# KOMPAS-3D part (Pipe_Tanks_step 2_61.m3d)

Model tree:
1. X Axis
2. Y Axis
3. Z Axis  (labels: Pipe Dn 50)
     Òîëùèíà ñòåíêè 1 = 1

Referenced files in C:\Documents and Settings\kashirsky\Мои документы\Camtasia Studio\Pipelines3D\Tanks\: Tanks_step 2.a3d
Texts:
  Pipe Dn 50
  Steel ASTM A295
  Three Point Plane
  Plane at Angle
  Line and Point Plane
  Axis through Two Vertices
  Axis of Feature
  Axis of Conical Surface
  Axis through Edge
  Trim by Surface
  Trim by Sketch
  Feature with No History
  Intersection Axis of Two Planes
  Two Line Plane
  Line and Face Plane
  Bend by line
  Hole in sheet body
  Cut in sheet body
  Point in CM
  Linear Dimension from Line to Point
  Surface Finish Symbol
  Geometric Tolerance Symbol
  Leader #1
  Leader #2
  Leader #3
  Shape Deviations and Datum
  Node point number
  Mark of coordination axis
  Node point designation
  Mark/Reference designation with leader
  Mark/reference designation on line
  Mark/Reference designation without leader
  Plane of section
